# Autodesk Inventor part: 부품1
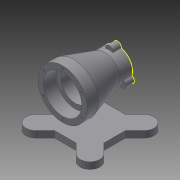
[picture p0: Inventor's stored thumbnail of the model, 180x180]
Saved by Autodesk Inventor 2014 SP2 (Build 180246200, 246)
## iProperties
Created: 2018-03
Part Number: 부품1
Material: Generic
Document SubType Name: Modeling
Designer: 거성
Density: 1 g/cm^3
Appearance: Default
Author: 거성
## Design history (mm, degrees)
sketch "스케치1" dims "d0" = 140
  geometry: L1 (0, 0)-(-49.497, 49.497); L2 (0, 0)-(-49.497, -49.497); L3 (0, 0)-(-70, 0); L4 (-35.239, 60.483)-(-19.755, 45); L5 (-60.483, 35.239)-(-45, 19.755); L6 (-19.755, -45)-(19.755, -45); L7 (45, -19.755)-(45, 19.755); L8 (19.755, 45)-(-19.755, 45); L9 (-45, 19.755)-(-45, -19.755); L10 (-45, -45)-(45, 45); L11 (49.497, -49.497)-(-45, 45); L12 (-35.239, -60.483)-(-19.755, -45); L13 (-60.483, -35.239)-(-45, -19.755); L14 (0, 0)-(54.385, 54.385); L15 (0, 0)-(70, 0); L16 (0, 0)-(60.568, -60.568); L17 (35.239, 60.483)-(19.755, 45); L18 (60.483, 35.239)-(45, 19.755); L19 (60.483, -35.239)-(45, -19.755); L20 (35.239, -60.483)-(19.755, -45); A1 r 18 centre (-49.497, -49.497) between (-60.483, -35.239) and (-35.239, -60.483); A2 r 18 centre (49.497, -49.497) between (35.239, -60.483) and (60.483, -35.239); A3 r 18 centre (-49.497, 49.497) between (-35.239, 60.483) and (-60.483, 35.239); A4 r 18 centre (49.497, 49.497) between (60.483, 35.239) and (35.239, 60.483); 1 further point
  constraints: 40 end point, 8 point on circle, 6 parallel, 6 perpendicular, 4 centre point, 4 point on line, 2 coincident, 2 horizontal, 1 midpoint, 16 other
  dimensions: "d1" = 45 deg angle of L3 L1; "d2" = 45 deg angle of L2 L3; "d4" = 18 radius of A1; "d5" = 90 distance between parallel lines of L6 L8; "d6" = 90 distance between parallel lines of L7 L9; "d7" = 45 deg angle of L15 L14; "d10" = 45 deg angle of L15 L16; "d11" = 18 radius of A2
extrude "돌출1" new body sketch "스케치1" distance "d12" = 12; taper "d13" = 0 deg
sketch "스케치2"
  geometry: L1 (82, 50)-(82, -50); L2 (0, -19.755)-(0, 19.755) reference; L3 (82, -50)-(109.5, -50); L4 (82, 50)-(127, 50); L5 (127, 50)-(127, 30); L6 (127, 30)-(109.5, -27); L7 (109.5, -27)-(109.5, -50); 3 further points
  constraints: 12 end point, 3 perpendicular, 2 midpoint, 1 horizontal alignment, 1 parallel, 1 vertical
  dimensions: "d14" = 82 distance between parallel lines of L1 L2; "d15" = 100 distance of L1.start L1.end; "d16" = 90 diameter of L5 L1; "d17" = 55 diameter of L7 L1; "d18" = 20 distance from line of L5.end L4; "d19" = 77 distance from line of L6.end L4
revolve "회전1" sketch "스케치2" stored, may be unused: angle "d20" = 90 deg
hole "구멍1" diameter "d23" = 70; stored, may be unused: countersink angle "d27" = 90 deg, drill point angle "d29" = 0 deg; dims "d21" = 10, "d22" = 10, "d24" = 6, "d25" = 4, "d26" = 2, "d28" = 23
hole "구멍2" diameter "d32" = 52; stored, may be unused: countersink angle "d36" = 90 deg, drill point angle "d38" = 0 deg; dims "d30" = 10, "d31" = 10, "d33" = 6, "d34" = 4, "d35" = 2, "d37" = 47
hole "구멍3" diameter "d41" = 40; stored, may be unused: countersink angle "d45" = 90 deg, drill point angle "d47" = 0 deg; dims "d39" = 10, "d40" = 10, "d42" = 6, "d43" = 4, "d44" = 2, "d46" = 30
sketch "스케치3"
  geometry: C1 r 20 at (0, 0) reference; A1 r 27.5 centre (0, 0) between (0, 27.5) and (-6.943, 26.609) reference; A2 r 7 centre (0, 27.5) between (6.943, 26.609) and (-6.943, 26.609); 1 further point
  constraints: 5 point on circle, 1 centre point, 1 vertical alignment
  dimensions: "d48" = 7 radius of A2
extrude "돌출2" join sketch "스케치3" distance "d49" = 15; taper "d50" = 0 deg
sketch "스케치4" dims "d54" = 80
  geometry: C1 r 35 at (0, 0) reference; C2 r 45 at (0, 0) reference; 3 further points
  constraints: 2 vertical alignment, 1 coincident, 2 other
hole "구멍4" sketch "스케치4" at (0, 40) diameter "d55" = 3.242; stored, may be unused: countersink angle "d59" = 90 deg, drill point angle "d61" = 118 deg; dims "d56" = 9, "d57" = 4, "d58" = 2, "d60" = 11
sketch "스케치5"
  geometry: C1 r 20 at (0, -27.5) reference; A1 r 27.5 centre (0, -27.5) between (-6.943, -0.891) and (-26.516, -34.792) reference; A2 r 7 centre (-23.816, -41.25) between (-26.516, -34.792) and (-19.573, -46.817) reference; A3 r 27.5 centre (0, -27.5) between (-19.573, -46.817) and (19.573, -46.817) reference; A4 r 7 centre (23.816, -41.25) between (19.573, -46.817) and (26.516, -34.792) reference; A5 r 27.5 centre (0, -27.5) between (26.516, -34.792) and (6.943, -0.891) reference; A6 r 7 centre (0, 0) between (6.943, -0.891) and (-6.943, -0.891) reference; 5 further points
  constraints: 2 coincident, 2 other
node "솔리드1"
pattern_circular "원형 패턴1" dims angle "d52" = 360 deg
pattern_circular "원형 패턴2" dims angle "d63" = 360 deg
other parameters: "d3" = 18, "d9" = 18
